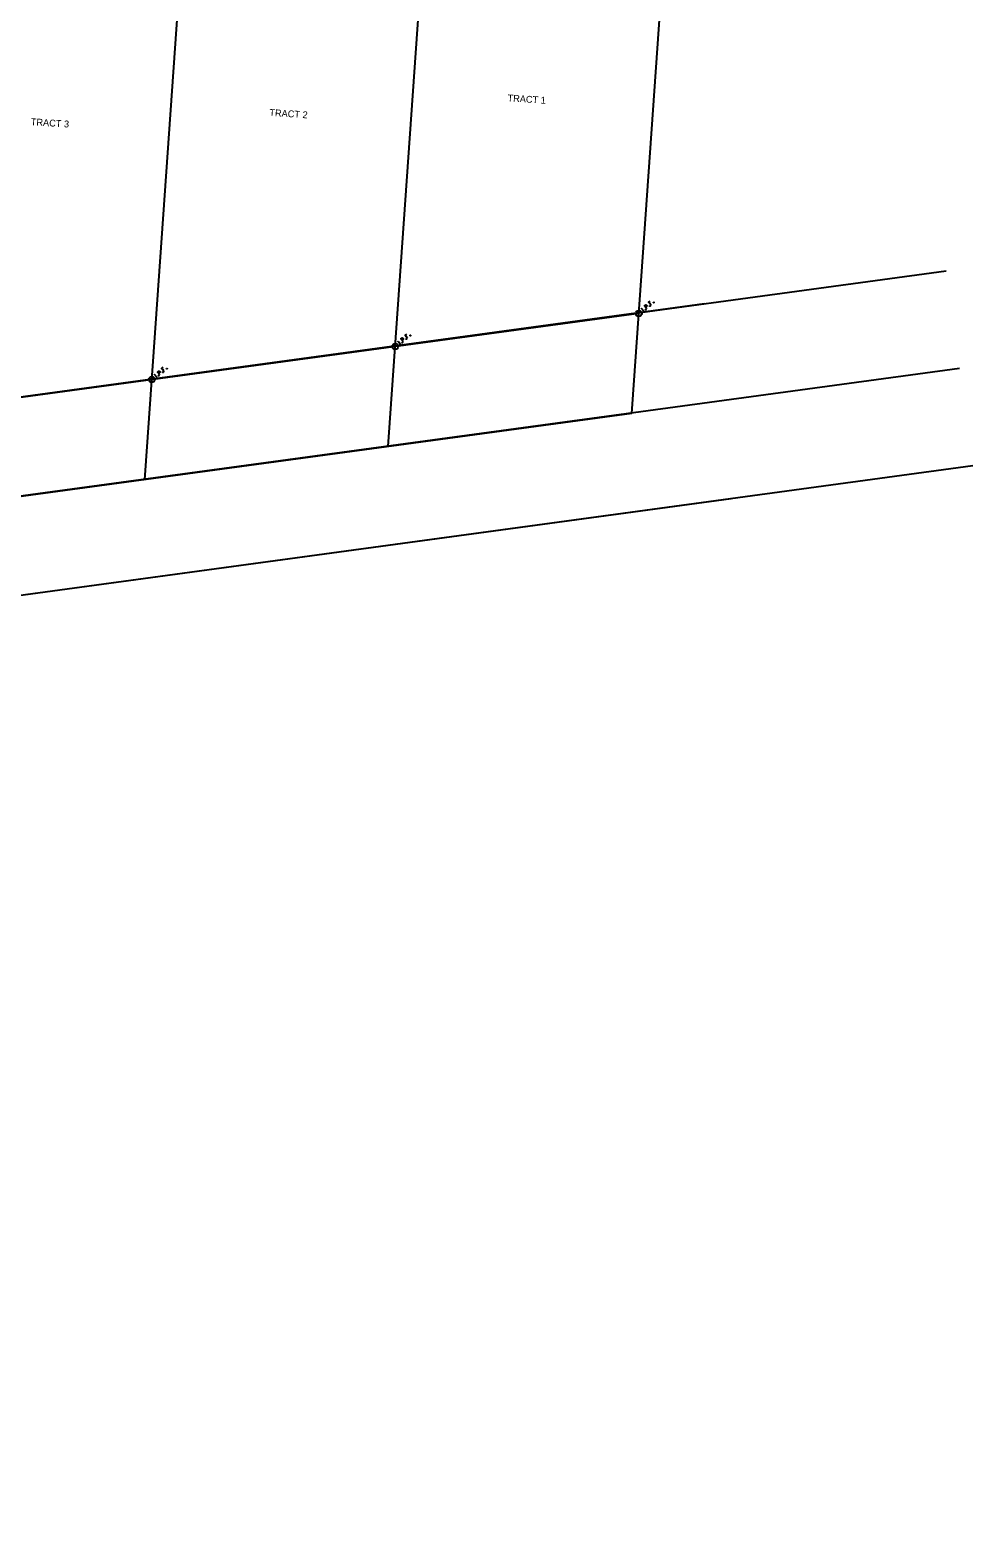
# Model space of a CAD drawing. Extents: x 1532954 to 1577849, y 698998 to 706606.
# Drawn here: x 1574585 to 1574969, y 702823 to 703437 of the extents above; entities that cross this region are included whole.
import ezdxf

# ---------------------------------------------------------------- set-up
doc = ezdxf.new("R2010")
doc.units = 0
for name, color, linetype in [('RW_X_Esmt_SH', 7, 'Continuous'), ('SC_Scratch10', 7, 'Continuous'), ('SC_Scratch3', 7, 'Continuous')]:
    doc.layers.add(name, color=color, linetype=linetype)

msp = doc.modelspace()

# ---------------------------------------------------------------- linework, layer by layer
at = {"layer": 'RW_X_Esmt_SH'}
for p, q in [((1574050.43, 703215.11), (1574859.76, 703325.41)), ((1571959, 702849.32), (1574870.56, 703246.15))]:
    msp.add_line(p, q, dxfattribs=at)
at = {"layer": 'SC_Scratch10'}
for p, q in [((1571190.11, 702825.26), (1574958.12, 703338.82)), ((1571190.11, 702825.26), (1574958.12, 703338.82)), ((1571190.11, 702825.26), (1574958.12, 703338.82)), ((1571195.51, 702785.63), (1574963.52, 703299.19)), ((1571200.91, 702745.99), (1574968.92, 703259.55))]:
    msp.add_line(p, q, dxfattribs=at)
at = {"layer": 'SC_Scratch3'}
for p, q in [((1574830.1, 703280.66), (1574882.16, 704019.69)), ((1574731.01, 703267.2), (1574783.07, 704006.23)), ((1574631.92, 703253.74), (1574683.98, 703992.77)), ((1574832.97, 703321.42), (1574040.25, 703213.72)), ((1574830.1, 703280.66), (1574037.38, 703172.96))]:
    msp.add_line(p, q, dxfattribs=at)
for points in [[(1574833.96, 703323.35), (1574834.22, 703323.58)], [(1574835.14, 703322.26), (1574834.09, 703323.47)], [(1574835.01, 703322.15), (1574835.28, 703322.38)], [(1574836.32, 703323.3), (1574835.27, 703324.5), (1574835.66, 703324.85), (1574835.71, 703324.87), (1574835.79, 703324.91), (1574835.83, 703324.91), (1574835.87, 703324.91), (1574835.95, 703324.89), (1574836.01, 703324.87), (1574836.09, 703324.81), (1574836.19, 703324.69), (1574836.22, 703324.65), (1574836.25, 703324.58), (1574836.28, 703324.48), (1574836.27, 703324.42), (1574836.26, 703324.38), (1574836.24, 703324.33), (1574836.18, 703324.26), (1574835.78, 703323.91)], [(1574835.72, 703323.06), (1574835.76, 703323.09), (1574835.81, 703323.1), (1574835.86, 703323.08), (1574835.91, 703323.03), (1574835.91, 703322.97), (1574835.91, 703322.93), (1574835.86, 703322.9), (1574835.82, 703322.89), (1574835.76, 703322.91), (1574835.72, 703322.96), (1574835.71, 703323.02), (1574835.72, 703323.06)], [(1574837.53, 703326.48), (1574836.96, 703325.98), (1574838.01, 703324.78)], [(1574837.41, 703324.54), (1574837.46, 703324.58), (1574837.5, 703324.58), (1574837.55, 703324.56), (1574837.6, 703324.52), (1574837.6, 703324.46), (1574837.6, 703324.42), (1574837.56, 703324.38), (1574837.51, 703324.38), (1574837.46, 703324.39), (1574837.41, 703324.44), (1574837.41, 703324.5), (1574837.41, 703324.54)], [(1574837.47, 703325.39), (1574837.88, 703325.75)], [(1574839.03, 703325.96), (1574839.07, 703325.99), (1574839.11, 703326), (1574839.17, 703325.98), (1574839.21, 703325.93), (1574839.22, 703325.87), (1574839.21, 703325.83), (1574839.17, 703325.8), (1574839.13, 703325.79), (1574839.07, 703325.81), (1574839.03, 703325.86), (1574839.02, 703325.92), (1574839.03, 703325.96)], [(1574734.87, 703309.89), (1574735.13, 703310.12)], [(1574736.05, 703308.8), (1574735, 703310)], [(1574735.92, 703308.69), (1574736.19, 703308.92)], [(1574737.23, 703309.83), (1574736.18, 703311.04), (1574736.57, 703311.39), (1574736.62, 703311.41), (1574736.7, 703311.44), (1574736.74, 703311.45), (1574736.78, 703311.45), (1574736.86, 703311.43), (1574736.92, 703311.41), (1574737.01, 703311.34), (1574737.1, 703311.23), (1574737.13, 703311.19), (1574737.16, 703311.11), (1574737.19, 703311.02), (1574737.18, 703310.96), (1574737.17, 703310.92), (1574737.15, 703310.87), (1574737.09, 703310.8), (1574736.69, 703310.45)], [(1574736.63, 703309.59), (1574736.67, 703309.63), (1574736.72, 703309.63), (1574736.77, 703309.62), (1574736.82, 703309.57), (1574736.82, 703309.51), (1574736.82, 703309.47), (1574736.77, 703309.43), (1574736.73, 703309.43), (1574736.68, 703309.45), (1574736.63, 703309.49), (1574736.63, 703309.55), (1574736.63, 703309.59)], [(1574738.44, 703313.02), (1574737.87, 703312.52), (1574738.92, 703311.32)], [(1574738.32, 703311.08), (1574738.37, 703311.11), (1574738.41, 703311.12), (1574738.47, 703311.1), (1574738.51, 703311.05), (1574738.52, 703310.99), (1574738.51, 703310.95), (1574738.47, 703310.92), (1574738.42, 703310.91), (1574738.37, 703310.93), (1574738.32, 703310.98), (1574738.32, 703311.04), (1574738.32, 703311.08)], [(1574738.38, 703311.93), (1574738.79, 703312.29)], [(1574739.94, 703312.49), (1574739.98, 703312.53), (1574740.02, 703312.53), (1574740.08, 703312.52), (1574740.12, 703312.47), (1574740.13, 703312.41), (1574740.12, 703312.37), (1574740.08, 703312.33), (1574740.04, 703312.33), (1574739.98, 703312.35), (1574739.94, 703312.39), (1574739.93, 703312.45), (1574739.94, 703312.49)], [(1574635.78, 703296.43), (1574636.04, 703296.66)], [(1574636.96, 703295.34), (1574635.91, 703296.54)], [(1574638.14, 703296.37), (1574637.09, 703297.57), (1574637.48, 703297.92), (1574637.53, 703297.95), (1574637.61, 703297.98), (1574637.65, 703297.98), (1574637.69, 703297.99), (1574637.77, 703297.97), (1574637.83, 703297.94), (1574637.92, 703297.88), (1574638.02, 703297.77), (1574638.04, 703297.72), (1574638.07, 703297.65), (1574638.1, 703297.56), (1574638.09, 703297.5), (1574638.08, 703297.46), (1574638.06, 703297.4), (1574638, 703297.33), (1574637.6, 703296.99)], [(1574639.35, 703299.56), (1574638.78, 703299.06), (1574639.83, 703297.85)], [(1574639.23, 703297.61), (1574639.28, 703297.65), (1574639.32, 703297.65), (1574639.38, 703297.64), (1574639.42, 703297.59), (1574639.43, 703297.53), (1574639.42, 703297.49), (1574639.38, 703297.45), (1574639.33, 703297.45), (1574639.28, 703297.47), (1574639.23, 703297.51), (1574639.23, 703297.57), (1574639.23, 703297.61)], [(1574639.29, 703298.47), (1574639.7, 703298.82)], [(1574640.85, 703299.03), (1574640.89, 703299.07), (1574640.93, 703299.07), (1574640.99, 703299.05), (1574641.03, 703299.01), (1574641.04, 703298.95), (1574641.03, 703298.91), (1574640.99, 703298.87), (1574640.95, 703298.87), (1574640.89, 703298.88), (1574640.85, 703298.93), (1574640.84, 703298.99), (1574640.85, 703299.03)], [(1574636.83, 703295.22), (1574637.1, 703295.45)], [(1574637.54, 703296.13), (1574637.59, 703296.17), (1574637.63, 703296.17), (1574637.68, 703296.15), (1574637.73, 703296.11), (1574637.73, 703296.05), (1574637.73, 703296.01), (1574637.69, 703295.97), (1574637.64, 703295.97), (1574637.59, 703295.98), (1574637.54, 703296.03), (1574637.54, 703296.09), (1574637.54, 703296.13)]]:
    msp.add_lwpolyline(points, dxfattribs=at)
for centre in [(1574832.97, 703321.42), (1574733.88, 703307.96), (1574634.79, 703294.5)]:
    msp.add_circle(centre, 1.2, dxfattribs=at)

# ---------------------------------------------------------------- texts
for s, p in [('TRACT 1', (1574779.51, 703407.8)), ('TRACT 3', (1574585.49, 703398.12)), ('TRACT 2', (1574682.58, 703401.87))]:
    msp.add_text(s, height=2.8, rotation=356.23722, dxfattribs=at).set_placement(p)

doc.saveas('drawing.dxf')
